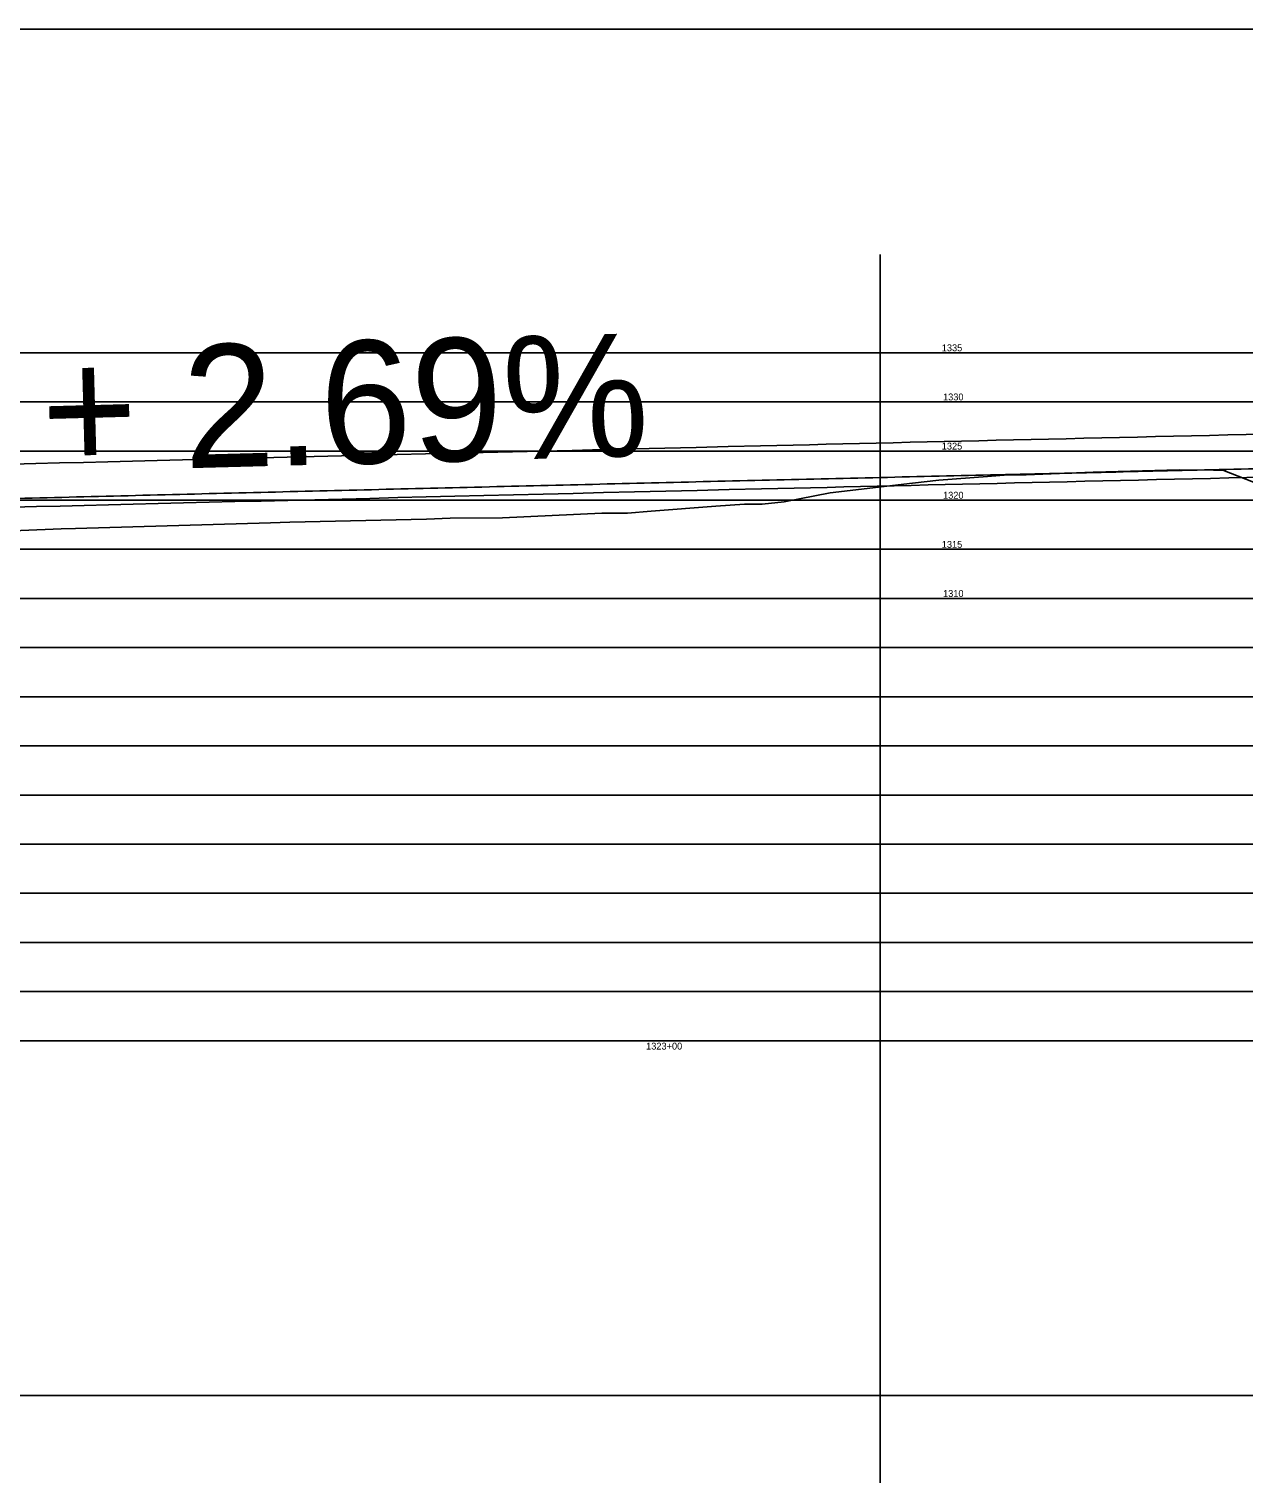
# Model space of a CAD drawing. Extents: x 680639 to 702326, y 743523 to 756592.
# Drawn here: x 688439.1 to 688562.8, y 751708.2 to 751856.1 of the extents above; entities that cross this region are included whole.
import ezdxf

# ---------------------------------------------------------------- set-up
doc = ezdxf.new("R2010")
doc.units = 0
for name, color, linetype in [('B_Concrete', 7, 'Continuous'), ('B_Proposed Ground', 7, 'Continuous'), ('Default', 7, 'Continuous'), ('R_Axis', 7, 'Continuous'), ('R_Axis Annot', 7, 'Continuous'), ('R_Exist Surface', 7, 'Continuous'), ('R_No Plot', 7, 'Continuous'), ('R_Vert Alg', 7, 'Continuous')]:
    doc.layers.add(name, color=color, linetype=linetype)

msp = doc.modelspace()

# ---------------------------------------------------------------- linework, layer by layer
at = {"layer": 'B_Concrete'}
msp.add_open_spline([(688372.96, 751810.2), (688384.35, 751810.5), (688420.74, 751811.44), (688507.13, 751813.6), (688632.13, 751816.46), (688757.14, 751819), (688844.65, 751820.6), (688882.16, 751821.24), (688897.6, 751821.51), (688900.54, 751821.56), (688903.48, 751821.61)], degree=3, dxfattribs=at)
at = {"layer": 'B_Proposed Ground'}
msp.add_line((688525.74, 751756.63), (688525.74, 751708.2), dxfattribs=at)
msp.add_open_spline([(688372.96, 751805.82), (688384.39, 751806.12), (688420.81, 751807.06), (688507.23, 751809.22), (688632.23, 751812.08), (688757.23, 751814.62), (688844.73, 751816.22), (688882.24, 751816.87), (688897.65, 751817.13), (688900.57, 751817.18), (688903.48, 751817.23)], degree=3, dxfattribs=at)
at = {"layer": 'R_Axis'}
for p, q in [((688525.74, 751753.19), (688525.74, 751833.19)), ((688372.96, 751823.19), (688903.48, 751823.19)), ((688372.96, 751818.19), (688903.48, 751818.19)), ((688372.96, 751813.19), (688903.48, 751813.19)), ((688372.96, 751808.19), (688903.48, 751808.19)), ((688372.96, 751803.19), (688903.48, 751803.19)), ((688372.96, 751798.19), (688903.48, 751798.19)), ((688372.96, 751793.19), (688903.48, 751793.19)), ((688372.96, 751788.19), (688903.48, 751788.19)), ((688372.96, 751783.19), (688903.48, 751783.19)), ((688372.96, 751778.19), (688903.48, 751778.19)), ((688372.96, 751773.19), (688903.48, 751773.19)), ((688372.96, 751768.19), (688903.48, 751768.19)), ((688372.96, 751763.19), (688903.48, 751763.19)), ((688372.96, 751758.19), (688903.48, 751758.19)), ((688372.96, 751753.19), (688903.48, 751753.19))]:
    msp.add_line(p, q, dxfattribs=at)
at = {"layer": 'R_Exist Surface'}
msp.add_line((688560.6, 751811.24), (688608.52, 751792.37), dxfattribs=at)
msp.add_lwpolyline([(688358.07, 751856.12), (688913.85, 751856.12), (688913.85, 751717.1), (688358.07, 751717.1)], close=True, dxfattribs=at)
msp.add_lwpolyline([(688427.61, 751804.66), (688442.4, 751805.27), (688443.88, 751805.32), (688463.7, 751805.9), (688465.67, 751805.94), (688479.6, 751806.26), (688481.99, 751806.35), (688487.31, 751806.39), (688497.44, 751806.85), (688500.05, 751806.87), (688502.43, 751807.08), (688509.02, 751807.59), (688511.95, 751807.78), (688513.73, 751807.79), (688515.96, 751808.03), (688520.66, 751808.92), (688529.03, 751809.93), (688531.71, 751810.24), (688536.65, 751810.59), (688538.75, 751810.77), (688540.58, 751810.76), (688547.42, 751811.03), (688549.95, 751811.1), (688556.15, 751811.26), (688559.65, 751811.24), (688560.6, 751811.24)], dxfattribs=at)
at = {"layer": 'R_Vert Alg'}
msp.add_spline([(688372.96, 751806.7), (688380.23, 751806.89), (688392.23, 751807.2), (688404.23, 751807.51), (688416.23, 751807.82), (688428.23, 751808.12), (688440.23, 751808.42), (688452.23, 751808.72), (688464.23, 751809.02), (688476.23, 751809.31), (688488.23, 751809.6), (688500.23, 751809.89), (688512.23, 751810.18), (688524.23, 751810.46), (688536.23, 751810.74), (688548.23, 751811.02), (688560.23, 751811.3), (688572.23, 751811.57), (688584.23, 751811.84), (688596.23, 751812.11), (688608.23, 751812.37), (688620.23, 751812.64), (688632.23, 751812.9), (688644.23, 751813.15), (688656.23, 751813.41), (688668.23, 751813.66), (688680.23, 751813.91), (688692.23, 751814.16), (688704.23, 751814.41), (688716.23, 751814.65), (688728.23, 751814.89), (688740.23, 751815.13), (688752.23, 751815.36), (688764.23, 751815.59), (688776.23, 751815.82), (688788.23, 751816.05), (688800.23, 751816.28), (688812.23, 751816.5), (688824.23, 751816.72), (688836.23, 751816.93), (688848.23, 751817.15), (688860.23, 751817.36), (688872.23, 751817.57), (688884.23, 751817.78), (688896.23, 751817.98), (688903.48, 751818.11)], degree=3, dxfattribs=at)

# ---------------------------------------------------------------- texts
at = {"layer": 'Default'}
msp.add_text('+ 2.69%', height=12.5, rotation=1.5409, dxfattribs=at).set_placement((688440.56, 751811.04))
at = {"layer": 'R_Axis Annot'}
msp.add_text('1323+00', height=0.7, dxfattribs=at).set_placement((688501.93, 751752.29))
at = {"layer": 'R_No Plot'}
for s, p in [('1335', (688532.01, 751823.34)), ('1330', (688532.14, 751818.34)), ('1325', (688532.01, 751813.34)), ('1320', (688532.14, 751808.34)), ('1315', (688532.01, 751803.34)), ('1310', (688532.14, 751798.34))]:
    msp.add_text(s, height=0.7, dxfattribs=at).set_placement(p)

doc.saveas('drawing.dxf')
